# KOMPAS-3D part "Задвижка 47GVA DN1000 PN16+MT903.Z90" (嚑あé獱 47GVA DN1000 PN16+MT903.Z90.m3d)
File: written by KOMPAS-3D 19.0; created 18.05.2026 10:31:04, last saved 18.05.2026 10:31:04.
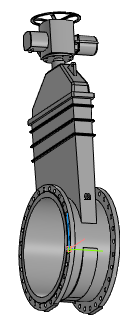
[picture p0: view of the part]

Document properties: Автор: Энергия; Полное имя файла: ..\Задвижка 47GVA DN40_DN1000+MT903.Z\Задвижка 47GVA DN1000 PN16+MT903.Z90.a3d

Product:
- Part/product: Задвижка 47GVA DN1000 PN16+MT903.Z90
    Масса: 2938.1
  - Body: Электропривод MT903.Z90-120
      Масса: 369.82
  - Body: Задвижка 47GVA DN1000 PN16_F25 без исполнительного механизма
      Масса: 2568.28

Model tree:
1. Операция без истории:1
2. Операция без истории:2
